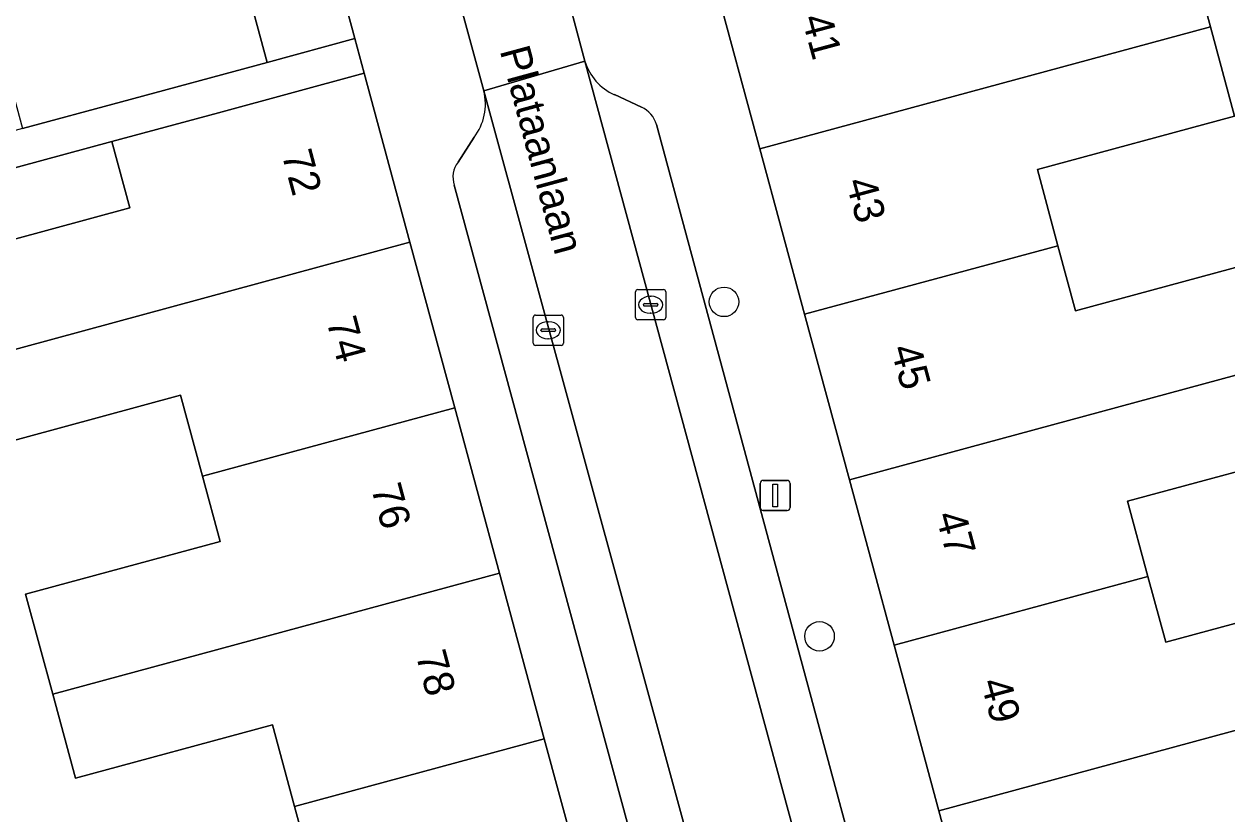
# Model space of a CAD drawing. Extents: x 159262 to 160143, y 383399 to 384319.
# Drawn here: x 159829 to 159868.84, y 383691.35 to 383717.49 of the extents above; entities that cross this region are included whole.
import ezdxf

# ---------------------------------------------------------------- set-up
doc = ezdxf.new("R2010")
doc.units = 0
for name, color, linetype in [('IMGEO_Boom', 7, 'Continuous'), ('IMGEO_Erf', 7, 'Continuous'), ('IMGEO_Kolk', 7, 'Continuous'), ('IMGEO_Lichtmast', 7, 'Continuous'), ('IMGEO_Openbare_ruimte_label', 7, 'Continuous'), ('IMGEO_Pand', 7, 'Continuous'), ('IMGEO_Pand_nummerreeks', 7, 'Continuous'), ('IMGEO_Parkeervlak_open', 7, 'Continuous'), ('IMGEO_Rijbaan_lokaal_open', 7, 'Continuous'), ('IMGEO_Voetpad_open', 7, 'Continuous')]:
    doc.layers.add(name, color=color, linetype=linetype)

msp = doc.modelspace()

# ---------------------------------------------------------------- linework, layer by layer
at = {"layer": 'IMGEO_Boom'}
for centre in [(159852.183, 383708.299), (159855.346, 383697.232)]:
    msp.add_circle(centre, 0.489, dxfattribs=at)
at = {"layer": 'IMGEO_Erf'}
for points in [[(159830.998, 383750.125), (159828.096, 383749.34), (159829.61, 383743.743), (159831.092, 383738.264), (159832.574, 383732.783), (159834.057, 383727.303), (159835.539, 383721.824), (159837.053, 383716.226), (159839.957, 383717.012)], [(159837.232, 383694.301), (159830.705, 383692.533), (159829.952, 383695.311), (159829.054, 383698.628), (159835.499, 383700.372), (159834.913, 383702.533), (159834.188, 383705.213), (159827.64, 383703.439), (159826.882, 383706.235), (159825.962, 383709.634), (159832.508, 383711.407), (159831.913, 383713.603), (159809.856, 383707.63), (159818.791, 383674.637), (159841.067, 383680.59), (159840.329, 383683.313), (159833.72, 383681.523), (159832.95, 383684.366), (159832.047, 383687.698), (159838.544, 383689.458), (159837.963, 383691.603)]]:
    msp.add_lwpolyline(points, close=True, dxfattribs=at)
for points in [[(159880.225, 383726.897), (159860.239, 383721.227), (159860.832, 383719.033), (159867.368, 383720.802), (159868.288, 383717.401), (159869.088, 383714.443), (159862.56, 383712.676), (159863.241, 383710.159), (159863.825, 383708.002), (159870.468, 383709.799)], [(159872.175, 383703.493), (159865.545, 383701.7), (159866.219, 383699.209), (159866.807, 383697.035), (159873.255, 383698.78)]]:
    msp.add_lwpolyline(points, dxfattribs=at)
at = {"layer": 'IMGEO_Kolk'}
for p, q in [((159849.253, 383707.779), (159849.253, 383708.631)), ((159849.328, 383708.705), (159850.18, 383708.705)), ((159849.741, 383708.485), (159849.766, 383708.485)), ((159850.254, 383708.631), (159850.254, 383707.779)), ((159849.512, 383708.199), (159849.512, 383708.211)), ((159849.95, 383708.162), (159849.552, 383708.162)), ((159849.555, 383708.248), (159849.953, 383708.248)), ((159849.996, 383708.211), (159849.996, 383708.199)), ((159845.862, 383706.935), (159845.862, 383707.787)), ((159845.937, 383707.861), (159846.789, 383707.861)), ((159846.35, 383707.641), (159846.375, 383707.641)), ((159846.863, 383707.787), (159846.863, 383706.935)), ((159850.18, 383707.705), (159849.328, 383707.705)), ((159849.764, 383707.925), (159849.739, 383707.925)), ((159846.121, 383707.355), (159846.121, 383707.367)), ((159846.559, 383707.318), (159846.161, 383707.318)), ((159846.164, 383707.404), (159846.562, 383707.404)), ((159846.605, 383707.367), (159846.605, 383707.355)), ((159846.789, 383706.861), (159845.937, 383706.861)), ((159846.373, 383707.081), (159846.348, 383707.081))]:
    msp.add_line(p, q, dxfattribs=at)
for points in [[(159849.253, 383707.779), (159849.253, 383708.631)], [(159849.328, 383708.705), (159850.18, 383708.705)], [(159850.254, 383708.631), (159850.254, 383707.779)], [(159845.862, 383706.935), (159845.862, 383707.787)], [(159845.937, 383707.861), (159846.789, 383707.861)], [(159846.863, 383707.787), (159846.863, 383706.935)], [(159850.18, 383707.705), (159849.328, 383707.705)], [(159846.789, 383706.861), (159845.937, 383706.861)]]:
    msp.add_lwpolyline(points, dxfattribs=at)
for centre, radius, start, end in [((159849.33, 383708.629), 0.0765, 91.552, 178.448), ((159849.33, 383708.629), 0.0765, 91.552, 178.448), ((159850.178, 383708.629), 0.0765, 1.552, 88.448), ((159850.178, 383708.629), 0.0765, 1.552, 88.448), ((159849.552, 383708.208), 0.0403, 85.8775, 175.7526), ((159849.549, 383708.198), 0.0366, 178.938, 274.7102), ((159849.953, 383708.205), 0.043, 264.8664, 352.4533), ((159849.957, 383708.21), 0.0386, 1.7309, 96.639), ((159845.939, 383707.785), 0.0765, 91.552, 178.448), ((159845.939, 383707.785), 0.0765, 91.552, 178.448), ((159846.787, 383707.785), 0.0765, 1.552, 88.448), ((159846.787, 383707.785), 0.0765, 1.552, 88.448), ((159849.33, 383707.781), 0.0765, 181.552, 268.448), ((159849.33, 383707.781), 0.0765, 181.552, 268.448), ((159850.178, 383707.781), 0.0765, 271.552, 358.448), ((159850.178, 383707.781), 0.0765, 271.552, 358.448), ((159846.161, 383707.364), 0.0403, 85.8775, 175.7526), ((159846.158, 383707.354), 0.0366, 178.938, 274.7102), ((159846.562, 383707.361), 0.043, 264.8664, 352.4533), ((159846.566, 383707.366), 0.0386, 1.7309, 96.639), ((159845.939, 383706.937), 0.0765, 181.552, 268.448), ((159845.939, 383706.937), 0.0765, 181.552, 268.448), ((159846.787, 383706.937), 0.0765, 271.552, 358.448), ((159846.787, 383706.937), 0.0765, 271.552, 358.448)]:
    msp.add_arc(centre, radius, start, end, dxfattribs=at)
for centre, major_axis, ratio, start_param, end_param in [((159849.74, 383708.205), (-0.387, 0.002), 0.722429, 4.712389, 7.853982), ((159849.765, 383708.205), (-0.39, 0.002), 0.717154, 1.570796, 4.712389), ((159846.349, 383707.361), (-0.387, 0.002), 0.722429, 4.712389, 7.853982), ((159846.374, 383707.361), (-0.39, 0.002), 0.717154, 1.570796, 4.712389)]:
    msp.add_ellipse(centre, major_axis=major_axis, ratio=ratio, start_param=start_param, end_param=end_param, dxfattribs=at)
at = {"layer": 'IMGEO_Lichtmast'}
for p, q in [((159853.484, 383702.393), (159854.274, 383702.393)), ((159854.274, 383702.393), (159853.484, 383702.393)), ((159853.384, 383701.493), (159853.384, 383702.293)), ((159853.384, 383702.293), (159853.384, 383701.493)), ((159854.374, 383702.293), (159854.374, 383701.493)), ((159854.374, 383701.493), (159854.374, 383702.293)), ((159854.274, 383701.393), (159853.484, 383701.393)), ((159853.484, 383701.393), (159854.274, 383701.393))]:
    msp.add_line(p, q, dxfattribs=at)
msp.add_lwpolyline([(159853.804, 383702.268), (159853.954, 383702.268), (159853.954, 383701.518), (159853.804, 383701.518), (159853.804, 383702.268)], dxfattribs=at)
for centre, start, end in [((159853.484, 383702.293), 90, 180), ((159853.484, 383702.293), 90, 180), ((159854.274, 383702.293), 0, 90), ((159854.274, 383702.293), 360, 90), ((159853.484, 383701.493), 180, 270), ((159853.484, 383701.493), 180, 270), ((159854.274, 383701.493), 270, 0), ((159854.274, 383701.493), 270, 0)]:
    msp.add_arc(centre, 0.1, start, end, dxfattribs=at)
at = {"layer": 'IMGEO_Pand'}
for points in [[(159835.539, 383721.824), (159820.946, 383717.876), (159820.82, 383717.841), (159821.66, 383714.735), (159828.28, 383716.525), (159828.954, 383714.035), (159832.236, 383714.923), (159837.053, 383716.226)], [(159867.368, 383720.802), (159860.832, 383719.033), (159860.239, 383721.227), (159856.677, 383720.262), (159851.854, 383718.957), (159853.368, 383713.364), (159868.288, 383717.401)], [(159869.088, 383714.443), (159868.288, 383717.401), (159853.368, 383713.364), (159854.85, 383707.888), (159863.241, 383710.159), (159862.56, 383712.676)], [(159840.267, 383715.866), (159835.443, 383714.559), (159831.913, 383713.603), (159832.508, 383711.407), (159825.962, 383709.634), (159826.882, 383706.235), (159827.022, 383706.273), (159841.782, 383710.272)], [(159841.782, 383710.272), (159827.022, 383706.273), (159826.882, 383706.235), (159827.64, 383703.439), (159834.188, 383705.213), (159834.913, 383702.533), (159835.081, 383702.579), (159843.265, 383704.796)], [(159870.468, 383709.799), (159863.825, 383708.002), (159863.241, 383710.159), (159854.85, 383707.888), (159856.332, 383702.412), (159871.367, 383706.48)], [(159865.545, 383701.7), (159872.175, 383703.493), (159871.367, 383706.48), (159856.332, 383702.412), (159857.813, 383696.936), (159866.219, 383699.209)], [(159843.265, 383704.796), (159835.081, 383702.579), (159834.913, 383702.533), (159835.499, 383700.372), (159829.054, 383698.628), (159829.952, 383695.311), (159844.748, 383699.319)], [(159844.748, 383699.319), (159829.952, 383695.311), (159830.705, 383692.533), (159837.232, 383694.301), (159837.963, 383691.603), (159838.084, 383691.635), (159846.232, 383693.843)], [(159873.255, 383698.78), (159866.807, 383697.035), (159866.219, 383699.209), (159857.813, 383696.936), (159859.296, 383691.459), (159874.149, 383695.478)], [(159868.53, 383690.723), (159874.965, 383692.464), (159874.149, 383695.478), (159859.296, 383691.459), (159860.809, 383685.867), (159865.632, 383687.172), (159869.227, 383688.145)], [(159846.232, 383693.843), (159838.084, 383691.635), (159837.963, 383691.603), (159838.544, 383689.458), (159832.047, 383687.698), (159832.95, 383684.366), (159847.716, 383688.367)]]:
    msp.add_lwpolyline(points, close=True, dxfattribs=at)
at = {"layer": 'IMGEO_Parkeervlak_open'}
for points in [[(159847.578, 383716.271), (159863.419, 383657.889)], [(159860.341, 383656.265), (159844.225, 383715.283)], [(159849.453, 383714.748), (159848.557, 383715.157)], [(159864.345, 383661.009), (159863.069, 383665.754), (159858.8, 383681.378), (159857.805, 383685.065), (159849.949, 383714.166)], [(159843.904, 383713.745), (159843.374, 383712.92)], [(159843.251, 383712.162), (159856.468, 383663.501), (159857.777, 383658.647)]]:
    msp.add_lwpolyline(points, dxfattribs=at)
for centre, radius, start, end in [((159849.242, 383716.746), 1.731, 195.9427, 246.6762), ((159842.497, 383714.841), 1.784, 322.082, 14.3398), ((159849.025, 383713.88), 0.968, 17.1631, 63.7144), ((159844.008, 383712.428), 0.802, 142.1977, 199.3683)]:
    msp.add_arc(centre, radius, start, end, dxfattribs=at)
at = {"layer": 'IMGEO_Rijbaan_lokaal_open'}
for points in [[(159847.578, 383716.271), (159846.785, 383719.216), (159843.395, 383718.296), (159843.432, 383718.191), (159844.225, 383715.283)], [(159847.578, 383716.271), (159844.225, 383715.283), (159860.341, 383656.265), (159860.54, 383655.346), (159863.868, 383656.237), (159863.832, 383656.347), (159863.419, 383657.889)]]:
    msp.add_lwpolyline(points, close=True, dxfattribs=at)
at = {"layer": 'IMGEO_Voetpad_open'}
for points in [[(159829.171, 383756.863), (159830.688, 383751.271), (159830.998, 383750.125), (159839.957, 383717.012), (159840.267, 383715.866), (159841.782, 383710.272), (159843.265, 383704.796), (159844.748, 383699.319), (159846.232, 383693.843), (159847.716, 383688.367), (159849.231, 383682.77), (159849.511, 383681.787), (159849.623, 383681.393), (159856.981, 383654.211), (159860.54, 383655.346), (159860.341, 383656.265)], [(159863.419, 383657.889), (159863.832, 383656.347), (159863.868, 383656.237), (159868.302, 383657.44), (159866.241, 383665.678), (159861.784, 383682.176), (159861.78, 383682.192), (159860.809, 383685.867), (159859.296, 383691.459), (159857.813, 383696.936), (159856.332, 383702.412), (159854.85, 383707.888), (159853.368, 383713.364), (159851.854, 383718.957), (159851.535, 383720.132), (159842.561, 383753.225)], [(159827.255, 383646.126), (159821.212, 383667.256), (159819.304, 383673.467), (159823.236, 383674.675), (159849.511, 383681.787), (159849.231, 383682.77), (159843.959, 383681.343), (159841.067, 383680.59), (159818.791, 383674.637), (159809.856, 383707.63), (159831.913, 383713.603), (159835.443, 383714.559), (159840.267, 383715.866), (159839.957, 383717.012), (159837.053, 383716.226), (159832.236, 383714.923), (159828.954, 383714.035), (159809.55, 383708.785), (159800.703, 383742.121)], [(159846.743, 383719.372), (159846.785, 383719.216), (159847.578, 383716.271)], [(159844.225, 383715.283), (159843.432, 383718.191)], [(159848.557, 383715.157), (159849.453, 383714.748)], [(159849.949, 383714.166), (159857.805, 383685.065), (159858.287, 383685.195), (159859.282, 383681.508), (159858.8, 383681.378), (159863.069, 383665.754), (159864.345, 383661.009)], [(159843.374, 383712.92), (159843.904, 383713.745)], [(159857.777, 383658.647), (159856.468, 383663.501), (159843.251, 383712.162)]]:
    msp.add_lwpolyline(points, dxfattribs=at)
for centre, radius, start, end in [((159849.242, 383716.746), 1.731, 195.9427, 246.6762), ((159842.497, 383714.841), 1.784, 322.082, 14.3398), ((159849.025, 383713.88), 0.968, 17.1631, 63.7144), ((159844.008, 383712.428), 0.802, 142.1977, 199.3683)]:
    msp.add_arc(centre, radius, start, end, dxfattribs=at)

# ---------------------------------------------------------------- texts
at = {"layer": 'IMGEO_Openbare_ruimte_label'}
msp.add_text('Plataanlaan', height=1, rotation=285.1898, dxfattribs=at).set_placement((159844.75, 383716.619))
at = {"layer": 'IMGEO_Pand_nummerreeks'}
for s, rotation, p in [('41', 285.0915, (159854.75, 383717.689)), ('72', 284.9941, (159837.531, 383713.189)), ('43', 285.0915, (159856.209, 383712.277)), ('74', 284.9941, (159839.011, 383707.665)), ('45', 285.0915, (159857.698, 383706.756)), ('76', 284.9941, (159840.49, 383702.144)), ('47', 285.0915, (159859.186, 383701.235)), ('78', 284.9941, (159841.97, 383696.62)), ('49', 285.0915, (159860.675, 383695.714))]:
    msp.add_text(s, height=1, rotation=rotation, dxfattribs=at).set_placement(p)

doc.saveas('drawing.dxf')
